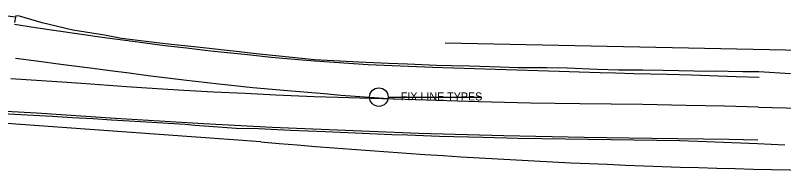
# Model space of a CAD drawing. Extents: x 1659932 to 1663108, y 619867 to 620611.
# Drawn here: x 1660213.5 to 1660482.2, y 620227.7 to 620281.8 of the extents above; entities that cross this region are included whole.
import ezdxf

# ---------------------------------------------------------------- set-up
doc = ezdxf.new("R2010")
doc.units = 0
for name, color, linetype in [('PM_X_CL_Dashed', 7, 'Continuous'), ('PM_X_CL_Double_Solid', 7, 'Continuous'), ('PM_X_Lane_Line', 7, 'Continuous'), ('PV_X_Curb', 7, 'Continuous'), ('PV_X_EOP', 7, 'Continuous'), ('RD_X_GR_Lt', 7, 'Continuous'), ('SC_Scratch6', 7, 'Continuous')]:
    doc.layers.add(name, color=color, linetype=linetype)

msp = doc.modelspace()

# ---------------------------------------------------------------- linework, layer by layer
at = {"layer": 'PM_X_CL_Dashed'}
msp.add_lwpolyline([(1660473.33, 620249.8), (1660569.82, 620247.52), (1660683.17, 620245.58), (1660845.9, 620242.37), (1660966.03, 620239.29), (1661085.35, 620237.14), (1661180.4, 620235.01), (1661204.65, 620234.52)], dxfattribs=at)
at = {"layer": 'PM_X_CL_Double_Solid'}
for points in [[(1660473.33, 620249.8), (1660461.46, 620250.11), (1660448.02, 620250.36), (1660432.81, 620250.67), (1660410.93, 620250.93), (1660393.62, 620251.25), (1660375.47, 620251.61), (1660346.02, 620252.54), (1660345.63, 620252.57), (1660327.31, 620253.91), (1660321.47, 620254.41), (1660308.67, 620255.47), (1660296.51, 620256.59), (1660284.59, 620257.84), (1660272.42, 620259.24), (1660259.91, 620260.76), (1660253.29, 620261.64), (1660246.65, 620262.5), (1660240.54, 620263.29), (1660229.39, 620264.71), (1660220.86, 620265.83), (1660213.5, 620266.78)], [(1660345.63, 620252.57), (1660326.3, 620253.2), (1660317.98, 620253.46), (1660304.58, 620253.99), (1660293.85, 620254.51), (1660282.78, 620255.07), (1660272.36, 620255.63), (1660263.03, 620256.2), (1660252.35, 620256.91), (1660236.63, 620258.02), (1660227.99, 620258.63), (1660211.88, 620259.64)]]:
    msp.add_lwpolyline(points, dxfattribs=at)
at = {"layer": 'PM_X_Lane_Line'}
for points in [[(1660473.6, 620260.18), (1660465.6, 620260.4), (1660449.9, 620260.91), (1660441.4, 620261.14), (1660429.76, 620261.44), (1660423.36, 620261.65), (1660417.95, 620261.81), (1660410.62, 620262.03), (1660403.6, 620262.24), (1660381.35, 620262.89), (1660359.36, 620263.6), (1660336.83, 620264.62), (1660318.26, 620265.83), (1660312.56, 620266.31), (1660308.45, 620266.68), (1660302.92, 620267.17), (1660294.7, 620268.02), (1660281.88, 620269.38), (1660279.89, 620269.58), (1660273.36, 620270.35), (1660265.77, 620271.25), (1660254.59, 620272.67), (1660243.84, 620274.09), (1660227.81, 620276.43), (1660220.57, 620277.48), (1660213.23, 620278.66)], [(1660473.08, 620238.32), (1660463.08, 620238.49), (1660436.04, 620238.92), (1660412.4, 620239.27), (1660384.34, 620239.85), (1660354.55, 620240.59), (1660303.33, 620242.65), (1660279.23, 620243.98), (1660248.56, 620245.89), (1660220.84, 620247.68), (1660203.63, 620248.69)]]:
    msp.add_lwpolyline(points, dxfattribs=at)
at = {"layer": 'PV_X_Curb'}
msp.add_lwpolyline([(1660213.54, 620281.17), (1660209.03, 620281.82)], dxfattribs=at)
at = {"layer": 'PV_X_EOP'}
for points in [[(1660484.61, 620261.47), (1660473.45, 620262.09), (1660467.89, 620262.12), (1660462.79, 620262.24), (1660458.72, 620262.36), (1660455.22, 620262.24), (1660450.78, 620262.32), (1660440.08, 620262.55), (1660432.97, 620262.69), (1660424.37, 620262.74), (1660417.04, 620262.97), (1660406.4, 620263.36), (1660399.17, 620263.51), (1660389.24, 620263.51), (1660383.03, 620263.76), (1660372.27, 620264.08), (1660366, 620264.23), (1660360.8, 620264.39), (1660350.61, 620264.81), (1660343.95, 620265.06), (1660333.62, 620265.45), (1660326.92, 620265.9), (1660318.06, 620266.37), (1660310.34, 620267.13), (1660297.75, 620268.4), (1660290.65, 620269.26), (1660277.09, 620270.7), (1660265.82, 620271.95), (1660250.61, 620273.71), (1660244.65, 620274.93), (1660233.58, 620276.64), (1660222.81, 620279.18), (1660214.91, 620281.61), (1660213.63, 620281.7), (1660213.54, 620281.17), (1660213.23, 620279.31)], [(1660482.53, 620236.51), (1660473.02, 620237.05), (1660452.19, 620237.77), (1660445.74, 620238), (1660405.87, 620238.65), (1660389.31, 620238.87), (1660376.92, 620239.23), (1660361.8, 620239.56), (1660350.62, 620239.98), (1660345.2, 620240.15), (1660334.89, 620240.66), (1660321.96, 620241.24), (1660309.62, 620241.67), (1660298.55, 620242.18), (1660290.7, 620242.39), (1660284.44, 620242.79), (1660276.27, 620243.36), (1660272.84, 620243.71), (1660257.4, 620244.63), (1660247.14, 620245.26), (1660240.67, 620245.7), (1660233.41, 620246.13), (1660226.37, 620246.52), (1660202.2, 620247.87)]]:
    msp.add_lwpolyline(points, dxfattribs=at)
at = {"layer": 'RD_X_GR_Lt'}
for p, q in [((1660363.83, 620272.19), (1660592.86, 620267.53)), ((1660299.33, 620237.69), (1660204.78, 620244.48))]:
    msp.add_line(p, q, dxfattribs=at)
msp.add_arc((1660533.65, 622926.05), 2698.56, 265.01858, 269.36013, dxfattribs=at)
at = {"layer": 'SC_Scratch6'}
msp.add_line((1660343.84, 620253.31), (1660376.64, 620253.31), dxfattribs=at)
msp.add_circle((1660340.6, 620253.31), 3.24, dxfattribs=at)

# ---------------------------------------------------------------- texts
msp.add_text('FIX LINE TYPES', height=2.8, dxfattribs=at).set_placement((1660348.27, 620252.14))

doc.saveas('drawing.dxf')
